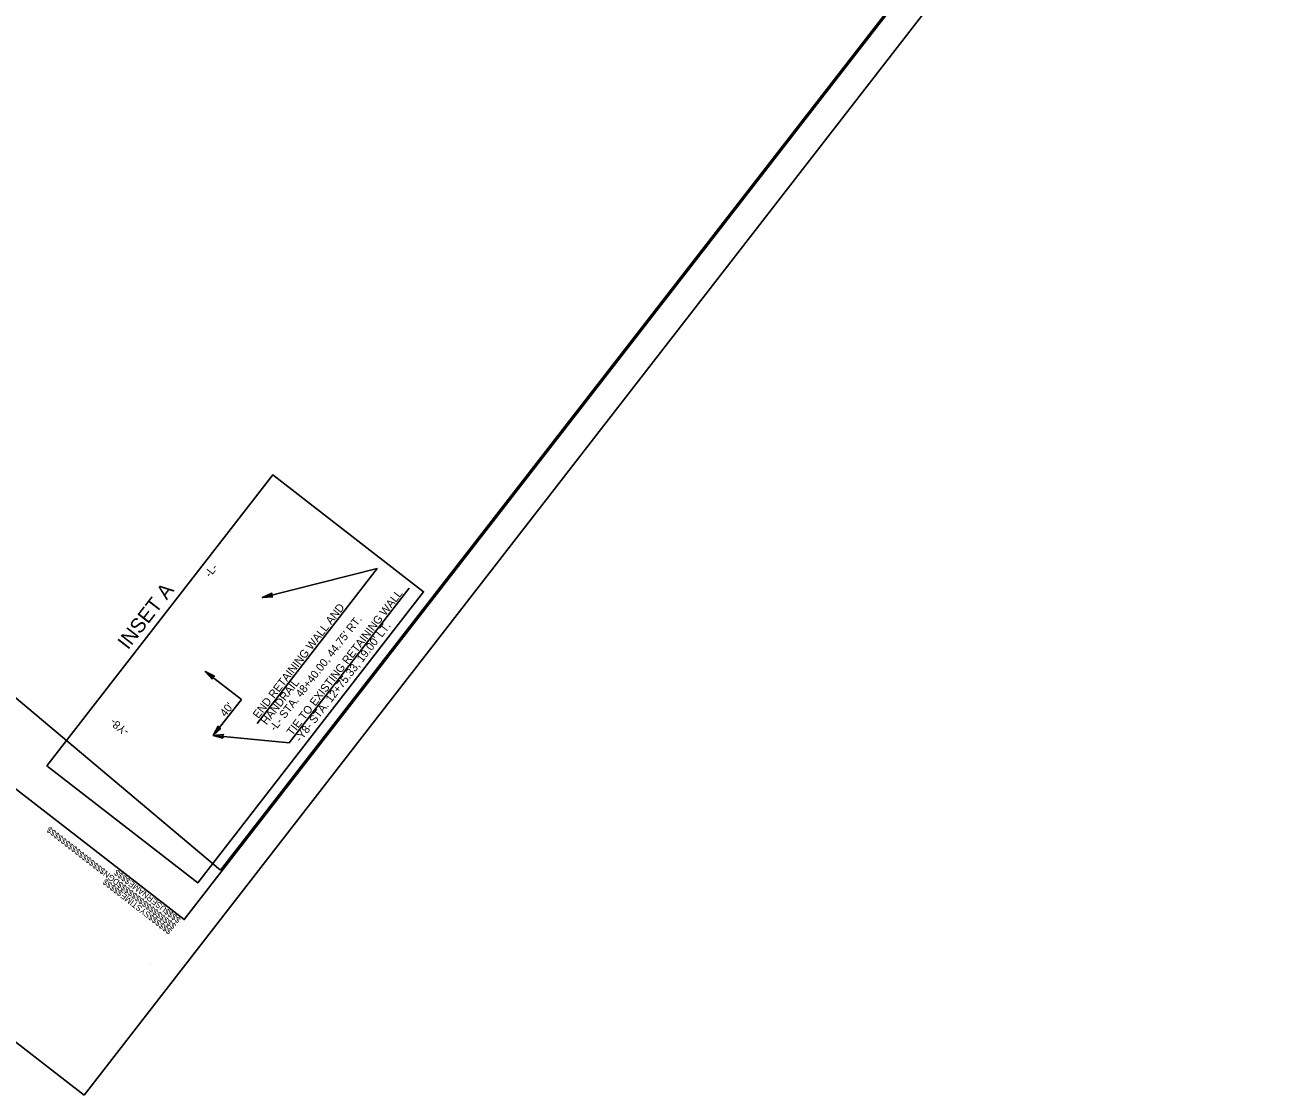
# Model space of a CAD drawing. Extents: x 2013373 to 2015284, y 444618 to 446636.
# Drawn here: x 2014190 to 2015284, y 444618 to 445555 of the extents above; entities that cross this region are included whole.
import ezdxf

# ---------------------------------------------------------------- set-up
doc = ezdxf.new("R2010")
doc.units = 0
for name, color, linetype in [('Exist PHM Road to be Removed Shape', 7, 'Continuous'), ('Prop Conc 5in Monolithic Keyed In Island', 7, 'Continuous'), ('Prop Horizontal Alignment', 7, 'Continuous'), ('Prop Horizontal Alignment Tick Small', 7, 'Continuous'), ('Prop Noise Wall', 7, 'Continuous'), ('Prop Paved Shoulder', 7, 'Continuous'), ('Prop Superelevation  Arrow CELL', 7, 'Continuous'), ('Scratch_Level_7', 7, 'Continuous')]:
    doc.layers.add(name, color=color, linetype=linetype)

msp = doc.modelspace()

# ---------------------------------------------------------------- linework, layer by layer
at = {"layer": 'Exist PHM Road to be Removed Shape'}
for points in [[(2014407, 445054.2), (2014397.9, 445053.5), (2014406.2, 445057.3), (2014405.5, 445055.4)], [(2014353.9, 444982.1), (2014347.8, 444988.9), (2014355.9, 444984.6), (2014354, 444984)], [(2014361.5, 444939), (2014354.8, 444932.8), (2014359.1, 444940.9), (2014359.6, 444939.1)], [(2014363.6, 444930.4), (2014354.8, 444932.8), (2014363.9, 444933.5), (2014362.6, 444932.1)]]:
    msp.add_lwpolyline(points, close=True, dxfattribs=at)
at = {"layer": 'Prop Conc 5in Monolithic Keyed In Island'}
msp.add_lwpolyline([(2014241.9, 444618), (2015283.7, 445961.4), (2014414.5, 446635.5), (2013372.7, 445292.2)], close=True, dxfattribs=at)
at = {"layer": 'Prop Horizontal Alignment'}
msp.add_line((2014299.8, 444733.5), (2014299.8, 444733.5), dxfattribs=at)
msp.add_line((2014299.8, 444733.5), (2014299.8, 444733.5), dxfattribs=at)
msp.add_line((2014299.8, 444733.5), (2014299.8, 444733.5), dxfattribs=at)
msp.add_line((2014299.8, 444733.5), (2014299.8, 444733.5), dxfattribs=at)
msp.add_line((2014299.8, 444733.5), (2014299.8, 444733.5), dxfattribs=at)
for points in [[(2014418.9, 446600.4), (2013499.7, 445415.1), (2014329.4, 444771.6), (2015248.7, 445957)], [(2014209.2, 444906.1), (2014406.9, 445160.9), (2014538.8, 445058.6), (2014341.2, 444803.7)]]:
    msp.add_lwpolyline(points, close=True, dxfattribs=at)
at = {"layer": 'Prop Horizontal Alignment Tick Small'}
msp.add_line((2014329.4, 444771.6), (2014329.4, 444771.6), dxfattribs=at)
at = {"layer": 'Prop Noise Wall'}
msp.add_lwpolyline([(2014144.5, 446243.4), (2013513.1, 445427.6), (2013603.8, 445375.4), (2013612.4, 445329.9), (2013915.8, 445258.4), (2014042, 445083.4), (2014361.1, 444814.9), (2015247.4, 445957.6), (2014564.2, 446487.5), (2014441.6, 446328.9), (2014350.5, 446399.7), (2014197.2, 446202.4)], close=True, dxfattribs=at)
at = {"layer": 'Scratch_Level_7'}
for p, q in [((2014393.1, 444943.4), (2014498.1, 445078.9)), ((2014397.9, 445053.5), (2014498.1, 445078.9)), ((2014421.1, 444926.4), (2014526.1, 445061.8)), ((2014347.8, 444988.9), (2014379.4, 444964.4)), ((2014354.8, 444932.8), (2014379.4, 444964.4)), ((2014421.1, 444926.4), (2014354.8, 444932.8))]:
    msp.add_line(p, q, dxfattribs=at)

# ---------------------------------------------------------------- texts
at = {"layer": 'Prop Horizontal Alignment Tick Small'}
for s, p in [('$$$$$$$$$$$$$$$$DGN$$$$$$$$$$$$$$$$', (2014322.8, 444767)), ('$$$$USERNAME$$$$', (2014326.9, 444772.2)), ('$$$$$$SYSTIME$$$$$', (2014319.1, 444762.3))]:
    msp.add_text(s, height=5.25, rotation=142.2051, dxfattribs=at).set_placement(p)
at = {"layer": 'Prop Paved Shoulder'}
for s, rotation, p in [('-L-', 52.2051, (2014352.1, 445070.6)), ('-Y8-', 142.1122, (2014281.8, 444937.4))]:
    msp.add_text(s, height=7, rotation=rotation, dxfattribs=at).set_placement(p)
at = {"layer": 'Prop Superelevation  Arrow CELL'}
for s, height, rotation, p in [('INSET A', 12.83, 52.2051, (2014280.2, 445007.2)), ('TIE TO EXISTING RETAINING WALL', 7, 52.2051, (2014424, 444932.1)), ('END RETAINING WALL AND', 7, 52.2051, (2014394.3, 444947.1)), ("-L- STA. 48+40.00, 44.75' RT. ", 7, 52.2051, (2014408.8, 444935.9)), ("-Y8- STA. 12+75.33, 19.00' LT. ", 7, 52.2051, (2014431.2, 444926.5)), ('HANDRAIL', 7, 52.2051, (2014401.5, 444941.5)), ("40'", 7, 51.9377, (2014365.5, 444948.6))]:
    msp.add_text(s, height=height, rotation=rotation, dxfattribs=at).set_placement(p)

doc.saveas('drawing.dxf')
